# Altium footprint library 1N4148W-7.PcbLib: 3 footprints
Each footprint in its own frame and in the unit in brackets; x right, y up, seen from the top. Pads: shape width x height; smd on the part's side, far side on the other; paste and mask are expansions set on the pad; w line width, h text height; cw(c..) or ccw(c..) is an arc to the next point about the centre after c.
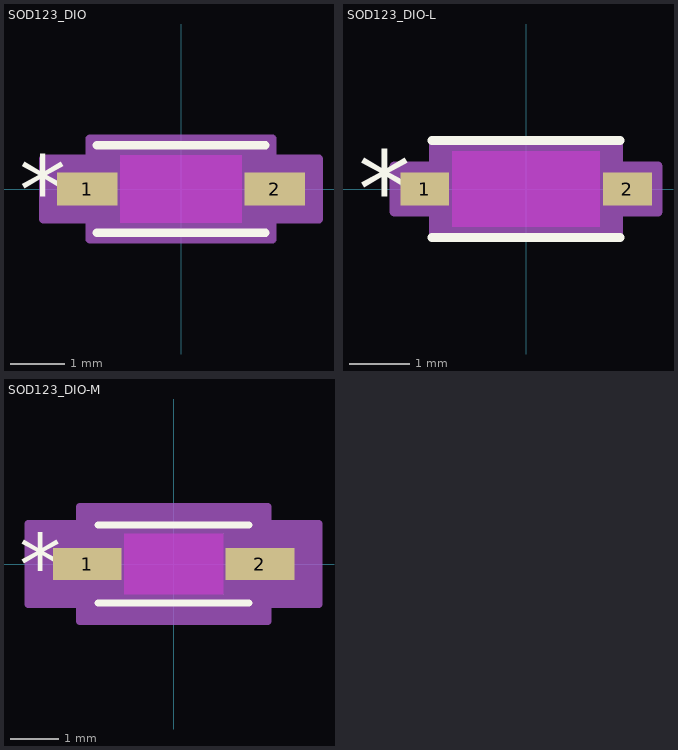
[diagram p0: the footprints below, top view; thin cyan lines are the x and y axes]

## SOD123_DIO [mm]
pads (2):
  rect 1.111x0.601 smd paste+0 mask+0: 1(-1.725,0) 2(1.725,0)
Top Overlay:
  lines w0.152: -1.552,-0.802 1.552,-0.802 ; -1.552,0.802 1.552,0.802
  text ".Designator" at -3.492,-0.635 h1.27
  text "*" at -2.979,-0.635 h1.27
Keep-Out Layer:
  region: -1.119,-0.624 -1.119,0.624 1.119,0.624 1.119,-0.624
Mechanical 13:
  lines w0.025: -1.425,-0.337 -1.087,-0.675 ; -1.425,0.337 -1.087,0.675 ; -1.925,-0.275 -1.925,0.275 -1.425,0.275 -1.425,-0.275 -1.925,-0.275 ; -1.425,-0.675 1.425,-0.675 1.425,0.675 -1.425,0.675 -1.425,-0.675 ; 1.425,-0.275 1.425,0.275 1.925,0.275 1.925,-0.275 1.425,-0.275
  text "*" at -1.488,-0.635 h1.27
  text ".Designator" at -3.492,-0.635 h1.27
Mechanical 15:
  region: -1.679,-0.554 -2.535,-0.554 -2.535,0.554 -1.679,0.554 -1.679,0.929 1.679,0.929 1.679,0.554 2.535,0.554 2.535,-0.554 1.679,-0.554 1.679,-0.929 -1.679,-0.929
  lines w0.152: -2.535,-0.554 -2.535,0.554 -1.679,0.554 -1.679,0.929 1.679,0.929 1.679,0.554 2.535,0.554 2.535,-0.554 1.679,-0.554 1.679,-0.929 -1.679,-0.929 -1.679,-0.554 -2.535,-0.554
3D body "SOD123_DIO.step": height 0.81, standoff 0, extent -1.925,-0.675 1.925,0.675

## SOD123_DIO-L [mm]
pads (2):
  rect 0.806x0.55 smd paste+0 mask+0: 1(-1.674,0) 2(1.674,0)
Top Overlay:
  lines w0.152: -1.552,-0.802 1.552,-0.802 ; -1.552,0.802 1.552,0.802
  text ".Designator" at -3.492,-0.635 h1.27
  text "*" at -2.776,-0.635 h1.27
Keep-Out Layer:
  region: -1.22,-0.624 -1.22,0.624 1.22,0.624 1.22,-0.624
Mechanical 13:
  lines w0.025: -1.425,-0.337 -1.087,-0.675 ; -1.425,0.337 -1.087,0.675 ; -1.925,-0.275 -1.925,0.275 -1.425,0.275 -1.425,-0.275 -1.925,-0.275 ; -1.425,-0.675 1.425,-0.675 1.425,0.675 -1.425,0.675 -1.425,-0.675 ; 1.425,-0.275 1.425,0.275 1.925,0.275 1.925,-0.275 1.425,-0.275
  text "*" at -1.488,-0.635 h1.27
  text ".Designator" at -3.492,-0.635 h1.27
Mechanical 15:
  region: -1.527,-0.377 -2.179,-0.377 -2.179,0.377 -1.527,0.377 -1.527,0.777 1.527,0.777 1.527,0.377 2.179,0.377 2.179,-0.377 1.527,-0.377 1.527,-0.777 -1.527,-0.777
  lines w0.152: -2.179,-0.377 -2.179,0.377 -1.527,0.377 -1.527,0.777 1.527,0.777 1.527,0.377 2.179,0.377 2.179,-0.377 1.527,-0.377 1.527,-0.777 -1.527,-0.777 -1.527,-0.377 -2.179,-0.377
3D body "SOD123_DIO.step": height 0.81, standoff 0, extent -1.925,-0.675 1.925,0.675

## SOD123_DIO-M [mm]
pads (2):
  rect 1.416x0.652 smd paste+0 mask+0: 1(-1.776,0) 2(1.776,0)
Top Overlay:
  lines w0.152: -1.552,-0.802 1.552,-0.802 ; -1.552,0.802 1.552,0.802
  text ".Designator" at -3.492,-0.635 h1.27
  text "*" at -3.182,-0.635 h1.27
Keep-Out Layer:
  region: -1.017,-0.624 -1.017,0.624 1.017,0.624 1.017,-0.624
Mechanical 13:
  lines w0.025: -1.425,-0.337 -1.087,-0.675 ; -1.425,0.337 -1.087,0.675 ; -1.925,-0.275 -1.925,0.275 -1.425,0.275 -1.425,-0.275 -1.925,-0.275 ; -1.425,-0.675 1.425,-0.675 1.425,0.675 -1.425,0.675 -1.425,-0.675 ; 1.425,-0.275 1.425,0.275 1.925,0.275 1.925,-0.275 1.425,-0.275
  text "*" at -1.488,-0.635 h1.27
  text ".Designator" at -3.492,-0.635 h1.27
Mechanical 15:
  region: -1.933,-0.834 -2.992,-0.834 -2.992,0.834 -1.933,0.834 -1.933,1.183 1.933,1.183 1.933,0.834 2.992,0.834 2.992,-0.834 1.933,-0.834 1.933,-1.183 -1.933,-1.183
  lines w0.152: -2.992,-0.834 -2.992,0.834 -1.933,0.834 -1.933,1.183 1.933,1.183 1.933,0.834 2.992,0.834 2.992,-0.834 1.933,-0.834 1.933,-1.183 -1.933,-1.183 -1.933,-0.834 -2.992,-0.834
3D body "SOD123_DIO.step": height 0.81, standoff 0, extent -1.925,-0.675 1.925,0.675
